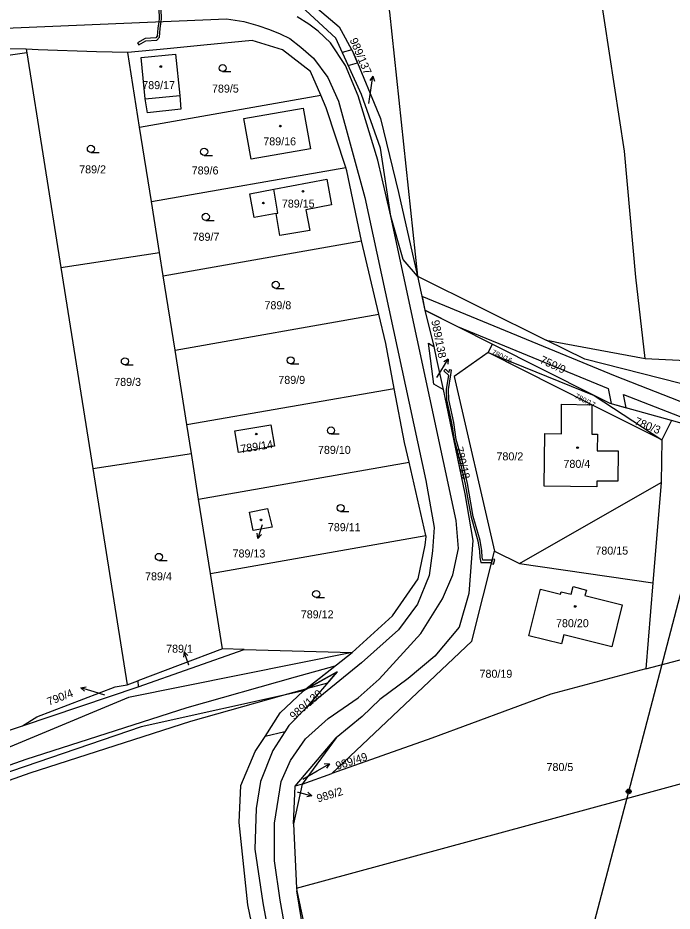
# Model space of a CAD drawing. Extents: x -757266 to -753360, y -1162585 to -1157740.
# Drawn here: x -756589.6 to -756450.6, y -1159460.9 to -1159271.1 of the extents above; entities that cross this region are included whole.
import ezdxf

# ---------------------------------------------------------------- set-up
doc = ezdxf.new("R2010")
doc.units = 0
for name, color, linetype in [('Hranice parcel', 7, 'Continuous'), ('Parcelní čísla', 7, 'Continuous'), ('Pop  PČ popisy', 7, 'Continuous'), ('Poz předměty', 7, 'Continuous'), ('Vnitřní kresba', 7, 'Continuous'), ('Věcná břemena k části', 7, 'Continuous'), ('Značky budov', 7, 'Continuous'), ('Značky kultur', 7, 'Continuous')]:
    doc.layers.add(name, color=color, linetype=linetype)

msp = doc.modelspace()

# ---------------------------------------------------------------- linework, layer by layer
at = {"layer": 'Hranice parcel'}
for p, q in [((-756587.67, -1159278.56), (-756591.62, -1159279.08)), ((-756587.8, -1159277.72), (-756587.67, -1159278.56)), ((-756587.67, -1159278.56), (-756580.44, -1159324.11)), ((-756563.69, -1159294.32), (-756566.2, -1159278.47)), ((-756563.69, -1159294.32), (-756525.23, -1159287.53)), ((-756561.18, -1159310.12), (-756563.69, -1159294.32)), ((-756561.18, -1159310.12), (-756519.93, -1159302.92)), ((-756559.48, -1159320.92), (-756561.18, -1159310.12)), ((-756558.68, -1159325.92), (-756516.57, -1159318.5)), ((-756512.9, -1159334.06), (-756516.57, -1159318.5)), ((-756580.44, -1159324.11), (-756559.48, -1159320.92)), ((-756558.68, -1159325.92), (-756559.48, -1159320.92)), ((-756580.44, -1159324.11), (-756573.65, -1159366.86)), ((-756556.17, -1159341.72), (-756558.68, -1159325.92)), ((-756504.65, -1159325.98), (-756477.34, -1159339.54)), ((-756504.65, -1159325.98), (-756503.1, -1159333.18)), ((-756488.8, -1159340.39), (-756503.1, -1159333.18)), ((-756503.1, -1159333.18), (-756501.23, -1159340.92)), ((-756556.17, -1159341.72), (-756512.9, -1159334.06)), ((-756488.8, -1159340.39), (-756489.7, -1159342.18)), ((-756467.13, -1159351.32), (-756488.8, -1159340.39)), ((-756477.34, -1159339.54), (-756456.32, -1159343.49)), ((-756553.67, -1159357.48), (-756556.17, -1159341.72)), ((-756489.7, -1159342.18), (-756467.13, -1159351.32)), ((-756456.32, -1159343.49), (-756425.7, -1159344.98)), ((-756553.67, -1159357.48), (-756509.62, -1159349.81)), ((-756467.13, -1159351.32), (-756452.81, -1159360.78)), ((-756552.7, -1159363.67), (-756553.67, -1159357.48)), ((-756450.73, -1159356.65), (-756452.81, -1159360.78)), ((-756436.85, -1159360.52), (-756450.73, -1159356.65)), ((-756452.81, -1159360.78), (-756452.96, -1159369.78)), ((-756573.65, -1159366.86), (-756552.7, -1159363.67)), ((-756551.16, -1159373.33), (-756552.7, -1159363.67)), ((-756551.16, -1159373.33), (-756506.48, -1159365.48)), ((-756502.92, -1159381.09), (-756506.48, -1159365.48)), ((-756573.65, -1159366.86), (-756566.35, -1159412.78)), ((-756483.03, -1159387.05), (-756452.96, -1159369.78)), ((-756452.96, -1159369.78), (-756454.72, -1159391.15)), ((-756548.66, -1159389.13), (-756551.16, -1159373.33)), ((-756548.66, -1159389.13), (-756502.92, -1159381.09)), ((-756488.34, -1159384.39), (-756483.03, -1159387.05)), ((-756483.03, -1159387.05), (-756454.72, -1159391.15)), ((-756546.12, -1159405.13), (-756548.66, -1159389.13)), ((-756454.72, -1159391.15), (-756456.22, -1159409.43)), ((-756456.22, -1159409.43), (-756429.39, -1159402.34)), ((-756546.12, -1159405.13), (-756564.06, -1159411.94)), ((-756563.99, -1159413.24), (-756541.48, -1159405.26)), ((-756541.48, -1159405.26), (-756546.12, -1159405.13)), ((-756541.48, -1159405.26), (-756518.53, -1159405.91)), ((-756528.91, -1159414.06), (-756518.53, -1159405.91)), ((-756588.6, -1159421.48), (-756563.99, -1159413.24)), ((-756568.86, -1159413.25), (-756566.35, -1159412.78)), ((-756566.35, -1159412.78), (-756564.06, -1159411.94)), ((-756564.06, -1159411.94), (-756563.99, -1159413.24)), ((-756600.59, -1159425.5), (-756588.6, -1159421.48)), ((-756532.84, -1159422.75), (-756537.05, -1159423.74)), ((-756530.66, -1159434.35), (-756521.93, -1159424.06)), ((-756521.93, -1159424.06), (-756529.15, -1159433.87)), ((-756529.15, -1159433.87), (-756522.86, -1159431.65)), ((-756529.15, -1159433.87), (-756530.99, -1159442.29)), ((-756529.15, -1159433.87), (-756530.66, -1159434.35)), ((-756530.99, -1159442.29), (-756530.66, -1159434.35)), ((-756530.99, -1159442.29), (-756530.36, -1159456.01)), ((-756530.36, -1159456.01), (-756530.33, -1159456.57)), ((-756523.75, -1159496.46), (-756530.33, -1159456.57))]:
    msp.add_line(p, q, dxfattribs=at)
for points in [[(-756456.32, -1159343.49), (-756458.35, -1159326.17), (-756460.69, -1159299.41), (-756468.18, -1159250.75), (-756472.78, -1159224.14), (-756479.57, -1159139.35)], [(-756521.72, -1159145.73), (-756522.81, -1159168.58), (-756522.73, -1159189.71), (-756520.08, -1159218.98), (-756510.6, -1159269.92), (-756504.65, -1159325.98)], [(-756504.65, -1159325.98), (-756507.74, -1159322.44), (-756510.32, -1159313.24), (-756512.54, -1159298.77), (-756516.6, -1159287.38), (-756522.03, -1159275.44), (-756534.74, -1159263.62)], [(-756534.74, -1159263.62), (-756525.9, -1159269.14), (-756521.33, -1159273), (-756518.25, -1159278.57), (-756512.56, -1159292.48), (-756508.71, -1159308.22), (-756504.65, -1159325.98)], [(-756525.23, -1159287.53), (-756527.43, -1159282.53), (-756533.33, -1159277.88), (-756539.82, -1159275.88), (-756550.09, -1159276.92), (-756557.82, -1159277.65), (-756566.2, -1159278.47)], [(-756587.8, -1159277.72), (-756599.38, -1159277.71), (-756603.4, -1159278.05)], [(-756566.2, -1159278.47), (-756572.88, -1159278.34), (-756585.24, -1159277.89), (-756587.8, -1159277.72)], [(-756555.15, -1159287.58), (-756554.98, -1159290.52), (-756562.05, -1159291.26), (-756562.49, -1159288.31), (-756563.37, -1159279.53), (-756556.07, -1159278.8), (-756555.15, -1159287.58)], [(-756519.93, -1159302.92), (-756524.06, -1159290.19), (-756525.23, -1159287.53)], [(-756528.95, -1159290.26), (-756527.4, -1159298.91), (-756540, -1159301.13), (-756541.56, -1159292.48), (-756528.95, -1159290.26)], [(-756516.57, -1159318.5), (-756516.89, -1159317.15), (-756519.71, -1159303.61), (-756519.93, -1159302.92)], [(-756539.38, -1159313.54), (-756540.32, -1159308.47), (-756535.23, -1159307.53), (-756523.94, -1159305.36), (-756522.93, -1159310.85), (-756528.4, -1159311.86), (-756527.58, -1159316.31), (-756533.9, -1159317.35), (-756534.67, -1159312.68), (-756539.38, -1159313.54)], [(-756509.62, -1159349.81), (-756511.44, -1159340.27), (-756512.9, -1159334.06)], [(-756499.25, -1159350.06), (-756501.23, -1159348.93), (-756502.34, -1159340.2), (-756501.23, -1159340.92)], [(-756501.23, -1159340.92), (-756500.62, -1159343.65), (-756499.25, -1159350.06)], [(-756432.66, -1159352.87), (-756469.17, -1159343.6), (-756477.34, -1159339.54)], [(-756489.7, -1159342.18), (-756496.92, -1159347.27), (-756488.34, -1159384.39)], [(-756452.81, -1159360.78), (-756467.66, -1159353.29), (-756489.7, -1159342.18)], [(-756499.25, -1159350.06), (-756498.15, -1159355.17), (-756494.62, -1159372.22), (-756492.93, -1159382.14), (-756493.76, -1159393.42), (-756495.85, -1159400.52), (-756501.02, -1159406.7), (-756506.7, -1159411.42), (-756512.7, -1159415.91), (-756516.47, -1159419.54), (-756521.93, -1159424.06)], [(-756506.48, -1159365.48), (-756507.43, -1159361.28), (-756509.62, -1159349.81)], [(-756450.73, -1159356.65), (-756463.8, -1159353), (-756467.13, -1159351.32)], [(-756467.66, -1159353.29), (-756467.69, -1159359.52), (-756466.49, -1159359.52), (-756466.51, -1159363.09), (-756462.06, -1159363.11), (-756462.12, -1159369.55), (-756466.57, -1159369.51), (-756466.58, -1159370.7), (-756477.76, -1159370.6), (-756477.67, -1159359.42), (-756474.12, -1159359.45), (-756474.08, -1159353.2), (-756467.66, -1159353.29)], [(-756543.49, -1159358.87), (-756535.84, -1159357.54), (-756535.05, -1159362.09), (-756542.7, -1159363.42), (-756543.49, -1159358.87)], [(-756535.57, -1159379.28), (-756539.6, -1159379.99), (-756540.38, -1159376.11), (-756536.51, -1159375.33), (-756535.57, -1159379.28)], [(-756518.53, -1159405.91), (-756509.96, -1159398.14), (-756504.53, -1159390.31), (-756503.04, -1159383.09), (-756502.87, -1159381.27), (-756502.92, -1159381.09)], [(-756522.86, -1159431.65), (-756493.17, -1159403.55), (-756488.34, -1159384.39)], [(-756471.65, -1159391.92), (-756468.82, -1159392.66), (-756469.12, -1159393.82), (-756461.19, -1159395.81), (-756463.43, -1159404.69), (-756473.61, -1159402.15), (-756474.11, -1159404.11), (-756481.02, -1159402.37), (-756478.55, -1159392.49), (-756474.3, -1159393.55), (-756474.17, -1159393.03), (-756472.07, -1159393.54), (-756471.65, -1159391.92)], [(-756518.53, -1159405.91), (-756566.06, -1159415.52), (-756603.63, -1159431.14), (-756679.86, -1159461.14), (-756714.68, -1159481.31), (-756722.84, -1159496.4), (-756730.02, -1159528.29)], [(-756456.22, -1159409.43), (-756476.36, -1159414.76), (-756501.63, -1159424.16), (-756522.86, -1159431.65)], [(-756528.91, -1159414.06), (-756521.75, -1159410.06), (-756528.46, -1159417.85)], [(-756588.6, -1159421.48), (-756585.51, -1159419.56), (-756568.86, -1159413.25)], [(-756528.91, -1159414.06), (-756563.38, -1159421.74), (-756601.97, -1159434.88), (-756678.44, -1159464.24), (-756712.18, -1159485.32), (-756717.75, -1159496.31), (-756721.03, -1159511.46)], [(-756537.05, -1159423.74), (-756533.85, -1159418.74), (-756528.91, -1159414.06)], [(-756528.46, -1159417.85), (-756532.01, -1159421.46), (-756532.84, -1159422.75)], [(-756516.91, -1159582.4), (-756517.98, -1159575.07), (-756525.87, -1159538.55), (-756531.41, -1159502.32), (-756536.4, -1159480.37), (-756540.71, -1159459.56), (-756542.58, -1159442.07), (-756542.22, -1159434.21), (-756539.13, -1159426.99), (-756537.05, -1159423.74)], [(-756530.36, -1159456.01), (-756461.88, -1159437.37), (-756424.94, -1159427.3)], [(-756530.33, -1159456.57), (-756524.34, -1159484.5), (-756522.02, -1159495.88)]]:
    msp.add_lwpolyline(points, dxfattribs=at)
at = {"layer": 'Pop  PČ popisy'}
for p, q in [((-756514.142, -1159283.458), (-756514.778, -1159284.38)), ((-756514.56, -1159286.43), (-756514.142, -1159283.458)), ((-756514.142, -1159283.458), (-756513.786, -1159284.52)), ((-756514.99, -1159289.32), (-756514.56, -1159286.43)), ((-756499.73, -1159346.13), (-756498.14, -1159343.585)), ((-756498.14, -1159343.585), (-756499.095, -1159344.169)), ((-756498.14, -1159343.585), (-756498.246, -1159344.7)), ((-756500.56, -1159347.47), (-756499.73, -1159346.13)), ((-756537.7, -1159378.81), (-756538.577, -1159381.68)), ((-756537.7, -1159378.8), (-756537.7, -1159378.81)), ((-756538.577, -1159381.68), (-756538.763, -1159380.576)), ((-756538.577, -1159381.68), (-756537.806, -1159380.869)), ((-756554.237, -1159405.783), (-756554.384, -1159406.892)), ((-756553.26, -1159408.62), (-756554.237, -1159405.783)), ((-756554.237, -1159405.783), (-756553.438, -1159406.566)), ((-756553.25, -1159408.64), (-756553.26, -1159408.62)), ((-756576.19, -1159413.403), (-756575.086, -1159413.217)), ((-756573.32, -1159414.28), (-756576.19, -1159413.403)), ((-756576.19, -1159413.403), (-756575.379, -1159414.174)), ((-756571.08, -1159414.97), (-756573.32, -1159414.28)), ((-756525.97, -1159431.07), (-756523.371, -1159429.57)), ((-756523.371, -1159429.57), (-756524.489, -1159429.637)), ((-756523.371, -1159429.57), (-756523.988, -1159430.504)), ((-756529.01, -1159432.86), (-756525.97, -1159431.07)), ((-756530.16, -1159435.59), (-756530.02, -1159435.63)), ((-756530.02, -1159435.63), (-756527.108, -1159436.356)), ((-756527.108, -1159436.356), (-756527.959, -1159435.628)), ((-756527.108, -1159436.356), (-756528.201, -1159436.6))]:
    msp.add_line(p, q, dxfattribs=at)
at = {"layer": 'Poz předměty'}
for p, q in [((-756459.83, -1159435.45), (-756441.27, -1159364.56)), ((-756477.46, -1159502.8), (-756459.83, -1159435.45))]:
    msp.add_line(p, q, dxfattribs=at)
for radius in [0.5, 0.4, 0.3, 0.2, 0.1]:
    msp.add_circle((-756459.8334, -1159435.4499), radius, dxfattribs=at)
at = {"layer": 'Vnitřní kresba'}
for p, q in [((-756527.78, -1159272.46), (-756530.26, -1159270.89)), ((-756640.33, -1159275.33), (-756545.28, -1159271.32)), ((-756545.28, -1159271.32), (-756541.56, -1159271.89)), ((-756541.56, -1159271.89), (-756538.62, -1159272.75)), ((-756538.62, -1159272.75), (-756536.14, -1159273.61)), ((-756525.77, -1159273.9), (-756527.78, -1159272.46)), ((-756536.14, -1159273.61), (-756533.82, -1159274.47)), ((-756533.82, -1159274.47), (-756531.81, -1159275.47)), ((-756523.16, -1159276.42), (-756525.77, -1159273.9)), ((-756531.81, -1159275.47), (-756529.44, -1159277.33)), ((-756519.95, -1159281.2), (-756523.16, -1159276.42)), ((-756529.44, -1159277.33), (-756526.79, -1159279.65)), ((-756526.79, -1159279.65), (-756523.72, -1159283.79)), ((-756517.3, -1159287.66), (-756519.95, -1159281.2)), ((-756523.72, -1159283.79), (-756521.48, -1159288.82)), ((-756562.49, -1159288.31), (-756555.15, -1159287.58)), ((-756513.11, -1159301.36), (-756517.3, -1159287.66)), ((-756521.48, -1159288.82), (-756515.9, -1159309.24)), ((-756510.32, -1159313.24), (-756513.11, -1159301.36)), ((-756534.32, -1159312.61), (-756535.23, -1159307.53)), ((-756515.9, -1159309.24), (-756502.89, -1159369.36)), ((-756534.67, -1159312.68), (-756534.32, -1159312.61)), ((-756496.5, -1159377.91), (-756510.32, -1159313.24)), ((-756502.89, -1159369.36), (-756501.12, -1159379.39)), ((-756495.97, -1159383.82), (-756496.5, -1159377.91)), ((-756501.12, -1159379.39), (-756501.47, -1159384.32)), ((-756501.47, -1159384.32), (-756502.18, -1159389.58)), ((-756497.21, -1159389.41), (-756495.97, -1159383.82)), ((-756502.18, -1159389.58), (-756504.67, -1159395.66)), ((-756499.34, -1159394.51), (-756497.21, -1159389.41)), ((-756504.67, -1159395.66), (-756508.75, -1159401.08)), ((-756503.96, -1159401.9), (-756499.34, -1159394.51)), ((-756508.75, -1159401.08), (-756516.57, -1159408.15)), ((-756512.84, -1159411.6), (-756503.96, -1159401.9)), ((-756516.57, -1159408.15), (-756528.46, -1159417.85)), ((-756517.28, -1159415.55), (-756512.84, -1159411.6)), ((-756523.67, -1159419.98), (-756517.28, -1159415.55)), ((-756528.46, -1159424.26), (-756523.67, -1159419.98)), ((-756532.84, -1159422.75), (-756535.39, -1159426.72)), ((-756531.66, -1159428.86), (-756528.46, -1159424.26)), ((-756535.39, -1159426.72), (-756538.05, -1159433.3)), ((-756533.61, -1159433.3), (-756531.66, -1159428.86)), ((-756538.05, -1159433.3), (-756538.94, -1159439.05)), ((-756535.05, -1159442.17), (-756533.61, -1159433.3)), ((-756538.94, -1159439.05), (-756539.2, -1159447.73)), ((-756535.03, -1159450.16), (-756535.05, -1159442.17)), ((-756539.2, -1159447.73), (-756537.54, -1159459.13)), ((-756533.85, -1159458.57), (-756535.03, -1159450.16)), ((-756520.88, -1159529.27), (-756533.85, -1159458.57)), ((-756537.54, -1159459.13), (-756524.34, -1159529.88))]:
    msp.add_line(p, q, dxfattribs=at)
at = {"layer": 'Věcná břemena k části'}
for points in [[(-756559.68, -1159267.16), (-756559.54, -1159271.26), (-756559.63, -1159271.93), (-756559.81, -1159273.3), (-756559.97, -1159275), (-756560.27, -1159275.33), (-756562.5, -1159275.48), (-756564.13, -1159276.42), (-756563.88, -1159276.85), (-756562.36, -1159275.98), (-756560.03, -1159275.81), (-756559.49, -1159275.22), (-756559.31, -1159273.36), (-756559.12, -1159271.9), (-756559.04, -1159271.28), (-756559.18, -1159267.16)], [(-756610.13, -1159439.7), (-756586.97, -1159431.52), (-756552.85, -1159420.54), (-756533.52, -1159415.09), (-756528.38, -1159413.65), (-756522.26, -1159408.84), (-756530.63, -1159411.16), (-756553.68, -1159417.67), (-756587.89, -1159428.67), (-756611.13, -1159436.88)]]:
    msp.add_lwpolyline(points, dxfattribs=at)
for points in [[(-756520.65, -1159278.47), (-756519.4, -1159281.23), (-756517.4, -1159280.64), (-756518.25, -1159278.57), (-756518.63, -1159277.87)], [(-756438.93, -1159354.91), (-756436.03, -1159353.97), (-756445.63, -1159353.88), (-756462.63, -1159347.2), (-756503.72, -1159330.28), (-756503.1, -1159333.18), (-756496.18, -1159336.67), (-756464.21, -1159349.81), (-756463.57, -1159353.06), (-756460.34, -1159353.97), (-756460.91, -1159351.12), (-756446.23, -1159356.88), (-756438.17, -1159356.95)], [(-756498.09, -1159347.01), (-756498.59, -1159350.02), (-756498.55, -1159352.27), (-756497.48, -1159357.15), (-756496.92, -1159360.75), (-756495.6, -1159365.51), (-756494.56, -1159370.15), (-756493.86, -1159374.23), (-756493.32, -1159377.17), (-756491.88, -1159382.23), (-756491.52, -1159384.37), (-756491.46, -1159385.73), (-756491.26, -1159386.83), (-756488.95, -1159386.8), (-756488.82, -1159386.3), (-756490.84, -1159386.33), (-756490.96, -1159385.67), (-756491.02, -1159384.31), (-756491.4, -1159382.11), (-756492.84, -1159377.05), (-756493.36, -1159374.15), (-756494.06, -1159370.05), (-756495.12, -1159365.39), (-756496.44, -1159360.65), (-756496.98, -1159357.05), (-756498.05, -1159352.21), (-756498.09, -1159350.06), (-756497.57, -1159346.96), (-756497.44, -1159345.93), (-756497.94, -1159345.87), (-756498.01, -1159346.41), (-756498.72, -1159345.74), (-756499.06, -1159346.1)], [(-756488.82, -1159386.3), (-756488.95, -1159386.8), (-756489.01, -1159387.04), (-756488.52, -1159387.16), (-756488.28, -1159386.19), (-756488.76, -1159386.07)], [(-756527.96, -1159413.53), (-756523.73, -1159412.36), (-756521.75, -1159410.06)]]:
    msp.add_lwpolyline(points, close=True, dxfattribs=at)
at = {"layer": 'Značky budov'}
for centre in [(-756559.1968, -1159281.4392), (-756533.8168, -1159294.1092), (-756529.0168, -1159307.9392), (-756537.4168, -1159310.4492), (-756538.9268, -1159359.5092), (-756470.6868, -1159362.4192), (-756537.9368, -1159377.7492), (-756471.1968, -1159396.1492)]:
    msp.add_circle(centre, 0.175, dxfattribs=at)
at = {"layer": 'Značky kultur'}
for p, q in [((-756546.063, -1159282.52), (-756544.313, -1159282.52)), ((-756574.043, -1159299.68), (-756572.293, -1159299.68)), ((-756549.993, -1159300.31), (-756548.243, -1159300.31)), ((-756549.643, -1159314.13), (-756547.893, -1159314.13)), ((-756534.783, -1159328.57), (-756533.033, -1159328.57)), ((-756566.823, -1159344.82), (-756565.073, -1159344.82)), ((-756531.623, -1159344.6), (-756529.873, -1159344.6)), ((-756523.053, -1159359.5), (-756521.303, -1159359.5)), ((-756521.013, -1159375.97), (-756519.263, -1159375.97)), ((-756559.603, -1159386.36), (-756557.853, -1159386.36)), ((-756526.203, -1159394.26), (-756524.453, -1159394.26))]:
    msp.add_line(p, q, dxfattribs=at)
for centre in [(-756546.0629, -1159281.7698), (-756574.0429, -1159298.9298), (-756549.9929, -1159299.5598), (-756549.6429, -1159313.3798), (-756534.7829, -1159327.8198), (-756531.6229, -1159343.8498), (-756566.8229, -1159344.0698), (-756523.0529, -1159358.7498), (-756521.0129, -1159375.2198), (-756559.6029, -1159385.6098), (-756526.2029, -1159393.5098)]:
    msp.add_circle(centre, 0.75, dxfattribs=at)

# ---------------------------------------------------------------- texts
at = {"layer": 'Parcelní čísla'}
for s, height, rotation, p in [('989/137', 1.7, 293, (-756519.132, -1159275.782)), ('989/138', 1.7, 281, (-756501.764, -1159335.462)), ('780/16', 1.1, 334, (-756489.071, -1159342.494)), ('759/9', 1.7, 335, (-756478.859, -1159344.34)), ('780/17', 1.1, 333, (-756471.389, -1159351.82)), ('780/3', 1.7, 338, (-756458.768, -1159357.448)), ('789/14', 1.7, 9, (-756542.137, -1159363.549)), ('780/18', 1.7, 283, (-756496.708, -1159362.431)), ('790/4', 1.7, 21, (-756582.954, -1159417.237)), ('989/130', 1.7, 41, (-756530.942, -1159420.331)), ('989/49', 1.7, 18, (-756521.757, -1159430.888)), ('989/2', 1.7, 17, (-756525.797, -1159437.794))]:
    msp.add_text(s, height=height, rotation=rotation, dxfattribs=at).set_placement(p)
for s, p in [('789/17', (-756563.137, -1159286.24)), ('789/5', (-756548.33, -1159286.98)), ('789/16', (-756537.43, -1159298.19)), ('789/2', (-756576.53, -1159304.14)), ('789/6', (-756552.64, -1159304.37)), ('789/15', (-756533.487, -1159311.41)), ('789/7', (-756552.45, -1159318.46)), ('789/8', (-756537.18, -1159333)), ('789/3', (-756569.09, -1159349.29)), ('789/9', (-756534.24, -1159348.86)), ('789/10', (-756525.82, -1159363.73)), ('780/2', (-756487.91, -1159365.11)), ('780/4', (-756473.69, -1159366.7)), ('789/11', (-756523.72, -1159380.15)), ('789/13', (-756543.955, -1159385.738)), ('780/15', (-756466.907, -1159385.13)), ('789/4', (-756562.54, -1159390.59)), ('789/12', (-756529.47, -1159398.67)), ('780/20', (-756475.267, -1159400.55)), ('789/1', (-756558.07, -1159405.97)), ('780/19', (-756491.507, -1159411.29)), ('780/5', (-756477.28, -1159431.11))]:
    msp.add_text(s, height=1.7, dxfattribs=at).set_placement(p)

doc.saveas('drawing.dxf')
